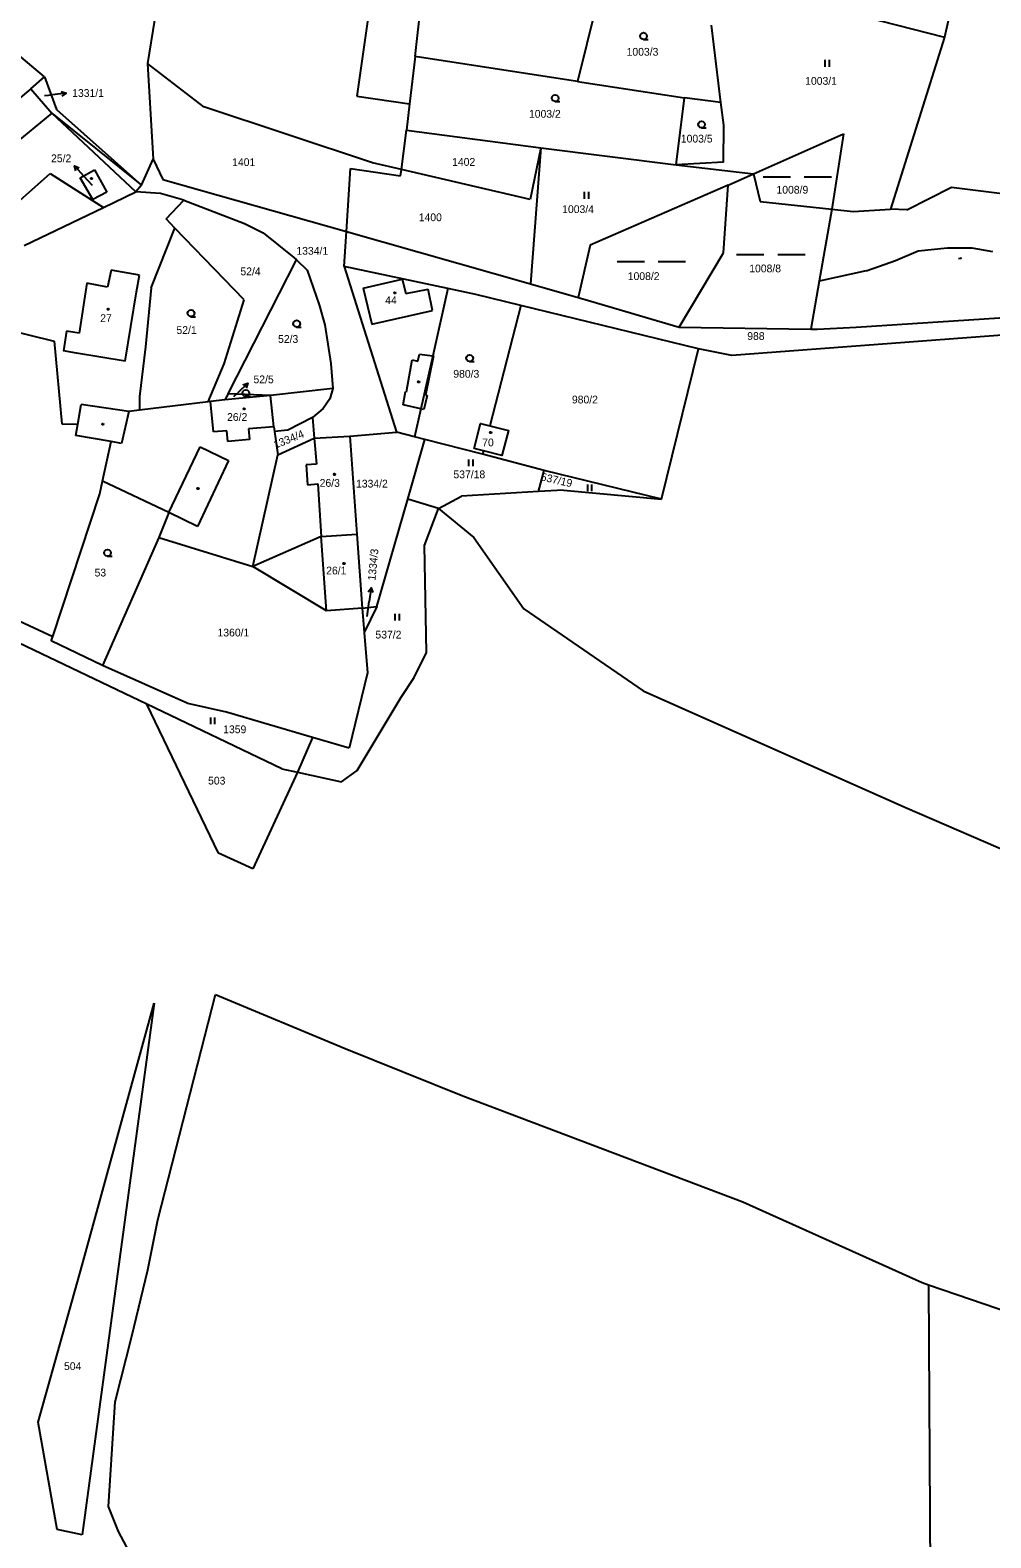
# Model space of a CAD drawing. Extents: x -852001 to -842497, y -1063614 to -1052182.
# Drawn here: x -844473.2 to -844262.9, y -1061856 to -1061526.1 of the extents above; entities that cross this region are included whole.
import ezdxf

# ---------------------------------------------------------------- set-up
doc = ezdxf.new("R2010")
doc.units = 0
for name, color, linetype in [('Default', 7, 'Continuous'), ('KN_HRANICE', 7, 'Continuous'), ('KN_KULTURY', 7, 'Continuous'), ('KN_PARCELY', 7, 'Continuous'), ('KN_SLUCKY', 7, 'Continuous')]:
    doc.layers.add(name, color=color, linetype=linetype)

# ---------------------------------------------------------------- blocks, each defined once
blk = doc.blocks.new('304')
at = {"layer": 'Default'}
blk.add_lwpolyline([(0, 0), (-0.38, 0.1), (-0.65, 0.37), (-0.75, 0.74), (-0.65, 1.11), (-0.38, 1.38), (-0.01, 1.48), (0.36, 1.38), (0.63, 1.11), (0.73, 0.73), (0.63, 0.35), (0.36, 0.08), (-0.02, -0.02), (0.98, -0.02)], dxfattribs=at)
blk = doc.blocks.new('306')
at = {"layer": 'Default'}
for p, q in [((-0.5, 1.5), (-0.5, 0)), ((0.5, 0), (0.5, 1.5))]:
    blk.add_line(p, q, dxfattribs=at)
blk = doc.blocks.new('NAHRADNI_SYMBOL')
at = {"layer": 'Default'}
blk.add_lwpolyline([(0.09, 0.15), (0.18, 0), (0.09, -0.15), (-0.09, -0.15), (-0.18, 0), (-0.09, 0.15), (0.09, 0.15)], dxfattribs=at)
blk = doc.blocks.new('803')
at = {"layer": 'Default'}
for p, q in [((-7.5, 0), (-1.5, 0)), ((1.5, 0), (7.5, 0))]:
    blk.add_line(p, q, dxfattribs=at)
blk = doc.blocks.new('10292')
at = {"layer": 'Default'}
blk.add_line((0, 3), (0, 0), dxfattribs=at)
blk.add_lwpolyline([(-0.5, 2), (0, 3), (0.5, 2)], dxfattribs=at)
blk = doc.blocks.new('402')
at = {"layer": 'Default'}
blk.add_lwpolyline([(0.09, 0.15), (0.18, 0), (0.09, -0.15), (-0.09, -0.15), (-0.18, 0), (-0.09, 0.15), (0.09, 0.15)], dxfattribs=at)
blk = doc.blocks.new('1060')
at = {"layer": 'Default'}
blk.add_line((-0.3, 0), (0.3, 0), dxfattribs=at)
blk.add_lwpolyline([(0.18, 0.04), (0.3, 0), (0.18, -0.04)], dxfattribs=at)

msp = doc.modelspace()

# ---------------------------------------------------------------- linework, layer by layer
at = {"layer": 'KN_HRANICE'}
for p, q in [((-844325.04, -1061514.23), (-844273.04, -1061527.65)), ((-844388.92, -1061531.86), (-844387.54, -1061520.17)), ((-844271.27, -1061519.86), (-844273.04, -1061527.65)), ((-844445.93, -1061523.92), (-844447.49, -1061533.39)), ((-844349.36, -1061521.16), (-844353.34, -1061537.33)), ((-844321.96, -1061541.94), (-844324.04, -1061525.01)), ((-844470, -1061536.35), (-844477.9, -1061529.66)), ((-844273.04, -1061527.65), (-844284.89, -1061565.27)), ((-844435.17, -1061542.92), (-844447.49, -1061533.39)), ((-844447.49, -1061533.39), (-844446.24, -1061554.35)), ((-844388.92, -1061531.86), (-844390.11, -1061542.25)), ((-844353.34, -1061537.33), (-844388.92, -1061531.86)), ((-844473.01, -1061538.94), (-844470, -1061536.35)), ((-844470, -1061536.35), (-844467.4, -1061543.5)), ((-844473.01, -1061538.94), (-844480.27, -1061544.97)), ((-844473.01, -1061538.94), (-844468.42, -1061544.28)), ((-844353.34, -1061537.33), (-844329.92, -1061540.93)), ((-844467.4, -1061543.5), (-844448.75, -1061560.05)), ((-844398.2, -1061555.11), (-844435.17, -1061542.92)), ((-844390.11, -1061542.25), (-844390.76, -1061547.96)), ((-844331.78, -1061555.55), (-844329.92, -1061540.93)), ((-844321.96, -1061541.94), (-844329.92, -1061540.93)), ((-844321.35, -1061546.91), (-844321.96, -1061541.94)), ((-844468.42, -1061544.28), (-844448.75, -1061560.05)), ((-844321.41, -1061554.97), (-844321.35, -1061546.91)), ((-844391.89, -1061556.58), (-844390.76, -1061547.96)), ((-844390.76, -1061547.96), (-844361.35, -1061551.88)), ((-844314.87, -1061557.58), (-844295.15, -1061548.77)), ((-844295.15, -1061548.77), (-844297.72, -1061565.27)), ((-844361.35, -1061551.88), (-844363.72, -1061563.16)), ((-844361.35, -1061551.88), (-844363.66, -1061581.64)), ((-844361.35, -1061551.88), (-844331.78, -1061555.55)), ((-844462.24, -1061558.4), (-844459.06, -1061556.7)), ((-844459.06, -1061556.7), (-844456.35, -1061561.53)), ((-844448.75, -1061560.05), (-844446.24, -1061554.35)), ((-844446.24, -1061554.35), (-844444.11, -1061558.8)), ((-844403.95, -1061570.2), (-844403.02, -1061556.36)), ((-844403.02, -1061556.36), (-844392.07, -1061557.99)), ((-844391.89, -1061556.58), (-844398.2, -1061555.11)), ((-844392.07, -1061557.99), (-844391.89, -1061556.58)), ((-844363.72, -1061563.16), (-844391.89, -1061556.58)), ((-844321.41, -1061554.97), (-844331.78, -1061555.55)), ((-844331.78, -1061555.55), (-844314.87, -1061557.58)), ((-844475.34, -1061563.31), (-844468.77, -1061557.5)), ((-844468.77, -1061557.5), (-844457.13, -1061564.94)), ((-844459.44, -1061563.15), (-844462.24, -1061558.4)), ((-844448.75, -1061560.05), (-844450, -1061561.52)), ((-844444.11, -1061558.8), (-844403.95, -1061570.2)), ((-844320.4, -1061560.02), (-844350.6, -1061573.17)), ((-844321.39, -1061574.83), (-844320.4, -1061560.02)), ((-844320.4, -1061560.02), (-844314.87, -1061557.58)), ((-844314.87, -1061557.58), (-844313.41, -1061563.61)), ((-844456.35, -1061561.53), (-844459.44, -1061563.15)), ((-844457.13, -1061564.94), (-844450, -1061561.52)), ((-844444.59, -1061561.88), (-844450, -1061561.52)), ((-844439.49, -1061563.31), (-844444.59, -1061561.88)), ((-844443.41, -1061567.42), (-844439.49, -1061563.31)), ((-844439.49, -1061563.31), (-844426.27, -1061568.44)), ((-844281.26, -1061565.4), (-844271.49, -1061560.45)), ((-844271.49, -1061560.45), (-844260.43, -1061561.87)), ((-844474.43, -1061573.26), (-844457.13, -1061564.94)), ((-844313.41, -1061563.61), (-844297.72, -1061565.27)), ((-844297.72, -1061565.27), (-844300.47, -1061581.03)), ((-844297.72, -1061565.27), (-844293.03, -1061565.76)), ((-844293.03, -1061565.76), (-844284.89, -1061565.27)), ((-844281.26, -1061565.4), (-844284.89, -1061565.27)), ((-844446.64, -1061582.48), (-844441.46, -1061569.44)), ((-844441.46, -1061569.44), (-844443.41, -1061567.42)), ((-844426.34, -1061585.08), (-844441.46, -1061569.44)), ((-844426.27, -1061568.44), (-844422.18, -1061570.43)), ((-844422.18, -1061570.43), (-844415.41, -1061575.89)), ((-844404.46, -1061577.82), (-844403.95, -1061570.2)), ((-844403.95, -1061570.2), (-844363.66, -1061581.64)), ((-844350.6, -1061573.17), (-844353.2, -1061584.61)), ((-844429.81, -1061605.69), (-844414.88, -1061576.38)), ((-844415.41, -1061575.89), (-844414.88, -1061576.38)), ((-844414.88, -1061576.38), (-844412.5, -1061578.61)), ((-844331.11, -1061591.08), (-844321.39, -1061574.83)), ((-844412.5, -1061578.61), (-844409.87, -1061586.18)), ((-844404.46, -1061577.82), (-844393, -1061614.07)), ((-844381.76, -1061582.63), (-844404.46, -1061577.82)), ((-844446.64, -1061582.48), (-844447.87, -1061595.38)), ((-844381.76, -1061582.63), (-844385.04, -1061597.34)), ((-844375.58, -1061583.94), (-844381.76, -1061582.63)), ((-844363.66, -1061581.64), (-844353.2, -1061584.61)), ((-844300.47, -1061581.03), (-844302.31, -1061591.53)), ((-844430.7, -1061599.13), (-844426.34, -1061585.08)), ((-844409.87, -1061586.18), (-844408.69, -1061590.57)), ((-844365.77, -1061586.33), (-844375.58, -1061583.94)), ((-844365.77, -1061586.33), (-844372.54, -1061612.69)), ((-844326.87, -1061595.82), (-844365.77, -1061586.33)), ((-844353.2, -1061584.61), (-844351.68, -1061585.04)), ((-844351.68, -1061585.04), (-844331.11, -1061591.08)), ((-844292.4, -1061591.06), (-844254.72, -1061588.66)), ((-844478.86, -1061591.44), (-844467.93, -1061594.19)), ((-844408.69, -1061590.57), (-844407.36, -1061599.06)), ((-844331.11, -1061591.08), (-844302.31, -1061591.53)), ((-844255.5, -1061592.46), (-844319.6, -1061597.27)), ((-844302.31, -1061591.53), (-844300.94, -1061591.55)), ((-844300.94, -1061591.55), (-844292.4, -1061591.06)), ((-844467.93, -1061594.19), (-844466.24, -1061612.23)), ((-844447.87, -1061595.38), (-844449.19, -1061606.24)), ((-844334.99, -1061628.71), (-844326.87, -1061595.82)), ((-844319.6, -1061597.27), (-844326.87, -1061595.82)), ((-844434.17, -1061607.4), (-844430.7, -1061599.13)), ((-844407.36, -1061599.06), (-844406.9, -1061604.52)), ((-844385.04, -1061597.34), (-844387.63, -1061608.98)), ((-844449.19, -1061606.24), (-844449.19, -1061609.24)), ((-844429.81, -1061605.69), (-844430.56, -1061607.03)), ((-844420.55, -1061606.03), (-844430.56, -1061607.03)), ((-844420.55, -1061606.03), (-844429.81, -1061605.69)), ((-844406.9, -1061604.52), (-844420.55, -1061606.03)), ((-844406.9, -1061604.52), (-844407.58, -1061606.77)), ((-844451.53, -1061609.53), (-844453.15, -1061616.52)), ((-844449.19, -1061609.24), (-844451.53, -1061609.53)), ((-844434.17, -1061607.4), (-844449.19, -1061609.24)), ((-844433.67, -1061607.34), (-844434.17, -1061607.4)), ((-844430.56, -1061607.03), (-844433.67, -1061607.34)), ((-844409.04, -1061608.91), (-844411.39, -1061610.86)), ((-844407.58, -1061606.77), (-844409.04, -1061608.91)), ((-844387.63, -1061608.98), (-844389, -1061615.11)), ((-844466.24, -1061612.23), (-844462.73, -1061612.31)), ((-844463.16, -1061614.78), (-844462.73, -1061612.31)), ((-844411.39, -1061610.86), (-844416.78, -1061613.62)), ((-844411.39, -1061610.86), (-844410.98, -1061615.41)), ((-844455.44, -1061616.12), (-844463.16, -1061614.78)), ((-844457.28, -1061624.8), (-844455.44, -1061616.12)), ((-844453.15, -1061616.52), (-844455.44, -1061616.12)), ((-844416.78, -1061613.62), (-844419.7, -1061613.9)), ((-844419.7, -1061613.9), (-844418.97, -1061619.01)), ((-844418.97, -1061619.01), (-844410.98, -1061615.41)), ((-844410.98, -1061615.41), (-844403.17, -1061614.92)), ((-844403.17, -1061614.92), (-844393, -1061614.07)), ((-844403.17, -1061614.92), (-844401.63, -1061636.37)), ((-844389, -1061615.11), (-844393, -1061614.07)), ((-844390.52, -1061628.76), (-844386.76, -1061615.69)), ((-844386.76, -1061615.69), (-844389, -1061615.11)), ((-844374.13, -1061618.87), (-844386.76, -1061615.69)), ((-844424.43, -1061643.44), (-844418.97, -1061619.01)), ((-844373.95, -1061618.15), (-844375.97, -1061617.63)), ((-844373.95, -1061618.15), (-844374.13, -1061618.87)), ((-844360.67, -1061622.48), (-844374.13, -1061618.87)), ((-844361.86, -1061627.06), (-844360.67, -1061622.48)), ((-844334.99, -1061628.71), (-844360.67, -1061622.48)), ((-844457.87, -1061627.58), (-844457.28, -1061624.8)), ((-844442.81, -1061631.67), (-844457.28, -1061624.8)), ((-844468.22, -1061658.79), (-844457.87, -1061627.58)), ((-844397.26, -1061652.22), (-844390.52, -1061628.76)), ((-844383.79, -1061630.77), (-844390.52, -1061628.76)), ((-844383.79, -1061630.77), (-844378.77, -1061628.06)), ((-844361.86, -1061627.06), (-844378.77, -1061628.06)), ((-844356.45, -1061626.74), (-844361.86, -1061627.06)), ((-844356.45, -1061626.74), (-844334.99, -1061628.71)), ((-844442.81, -1061631.67), (-844445.01, -1061637.13)), ((-844386.84, -1061638.84), (-844383.79, -1061630.77)), ((-844383.79, -1061630.77), (-844376.04, -1061637.09)), ((-844445.01, -1061637.13), (-844457.31, -1061665.08)), ((-844445.01, -1061637.13), (-844424.43, -1061643.44)), ((-844409.45, -1061636.9), (-844424.43, -1061643.44)), ((-844409.45, -1061636.9), (-844401.63, -1061636.37)), ((-844401.63, -1061636.37), (-844400.47, -1061652.6)), ((-844386.4, -1061662.29), (-844386.84, -1061638.84)), ((-844376.04, -1061637.09), (-844365.11, -1061652.71)), ((-844498.37, -1061644.75), (-844468.22, -1061658.79)), ((-844408.29, -1061653.16), (-844424.43, -1061643.44)), ((-844447.63, -1061673.57), (-844500.09, -1061648.51)), ((-844400.47, -1061652.6), (-844397.26, -1061652.22)), ((-844397.26, -1061652.22), (-844400.04, -1061657.86)), ((-844400.47, -1061652.6), (-844408.29, -1061653.16)), ((-844400.47, -1061652.6), (-844400.04, -1061657.86)), ((-844365.11, -1061652.71), (-844338.96, -1061670.68)), ((-844468.52, -1061659.69), (-844468.22, -1061658.79)), ((-844400.04, -1061657.86), (-844399.31, -1061666.7)), ((-844457.31, -1061665.08), (-844468.52, -1061659.69)), ((-844389.07, -1061667.77), (-844386.4, -1061662.29)), ((-844438.63, -1061673.4), (-844457.31, -1061665.08)), ((-844399.31, -1061666.7), (-844403.35, -1061683.2)), ((-844391.94, -1061672.06), (-844389.07, -1061667.77)), ((-844401.55, -1061688.12), (-844391.94, -1061672.06)), ((-844338.96, -1061670.68), (-844281.72, -1061696.14)), ((-844418.06, -1061687.7), (-844447.63, -1061673.57)), ((-844431.96, -1061706.15), (-844447.63, -1061673.57)), ((-844430.19, -1061675.35), (-844438.63, -1061673.4)), ((-844411.36, -1061680.86), (-844430.19, -1061675.35)), ((-844411.36, -1061680.86), (-844414.65, -1061688.46)), ((-844403.35, -1061683.2), (-844411.36, -1061680.86)), ((-844414.65, -1061688.46), (-844424.45, -1061709.57)), ((-844418.06, -1061687.7), (-844414.65, -1061688.46)), ((-844414.65, -1061688.46), (-844405.04, -1061690.59)), ((-844405.04, -1061690.59), (-844401.55, -1061688.12)), ((-844281.72, -1061696.14), (-844251.79, -1061709.03)), ((-844424.45, -1061709.57), (-844431.96, -1061706.15)), ((-844445.21, -1061786.38), (-844432.58, -1061737.13)), ((-844432.58, -1061737.13), (-844404.23, -1061748.89)), ((-844446.01, -1061738.96), (-844461.75, -1061855.31)), ((-844461.75, -1061796.28), (-844446.01, -1061738.96)), ((-844404.23, -1061748.89), (-844378.49, -1061759.27)), ((-844378.49, -1061759.27), (-844317.17, -1061782.48)), ((-844317.17, -1061782.48), (-844277.96, -1061800.13)), ((-844447.39, -1061797.31), (-844445.21, -1061786.38)), ((-844471.43, -1061830.64), (-844461.75, -1061796.28)), ((-844450.86, -1061811.85), (-844447.39, -1061797.31)), ((-844277.96, -1061800.13), (-844276.55, -1061800.61)), ((-844276.55, -1061800.61), (-844242.58, -1061812.17)), ((-844276.55, -1061800.61), (-844275.61, -1061955.01)), ((-844454.58, -1061826.21), (-844450.86, -1061811.85)), ((-844455.99, -1061849.08), (-844454.58, -1061826.21)), ((-844467.25, -1061854.17), (-844471.43, -1061830.64)), ((-844453.81, -1061854.57), (-844455.99, -1061849.08)), ((-844461.75, -1061855.31), (-844467.25, -1061854.17)), ((-844441.86, -1061877.08), (-844453.81, -1061854.57))]:
    msp.add_line(p, q, dxfattribs=at)
for points in [[(-844375.97, -1061617.63), (-844374.57, -1061612.18), (-844372.54, -1061612.69)], [(-844372.54, -1061612.69), (-844368.49, -1061613.72), (-844369.9, -1061619.19), (-844373.95, -1061618.15)]]:
    msp.add_lwpolyline(points, dxfattribs=at)
at = {"layer": 'KN_PARCELY'}
for p, q in [((-844470.04, -1061540.44), (-844468.27, -1061540.25)), ((-844459.49, -1061560.13), (-844461.41, -1061558.03)), ((-844428.56, -1061606.28), (-844427.68, -1061605.44)), ((-844399.36, -1061654.37), (-844398.93, -1061651.08))]:
    msp.add_line(p, q, dxfattribs=at)
at = {"layer": 'KN_SLUCKY'}
for p, q in [((-844399.03, -1061522.17), (-844401.68, -1061540.59)), ((-844401.68, -1061540.59), (-844390.11, -1061542.25)), ((-844468.42, -1061544.28), (-844475.84, -1061550.39)), ((-844450, -1061561.52), (-844468.42, -1061544.28)), ((-844287.3, -1061577.72), (-844283.8, -1061576.51)), ((-844283.8, -1061576.51), (-844278.78, -1061574.38)), ((-844278.78, -1061574.38), (-844272.39, -1061573.77)), ((-844272.39, -1061573.77), (-844267.07, -1061573.77)), ((-844267.07, -1061573.77), (-844262.5, -1061574.53)), ((-844455.44, -1061578.66), (-844456.23, -1061582.31)), ((-844449.21, -1061579.73), (-844455.44, -1061578.66)), ((-844449.84, -1061583.39), (-844449.21, -1061579.73)), ((-844290.2, -1061578.79), (-844300.47, -1061581.03)), ((-844290.2, -1061578.79), (-844287.3, -1061577.72)), ((-844460.74, -1061581.49), (-844462.44, -1061592.38)), ((-844456.23, -1061582.31), (-844460.74, -1061581.49)), ((-844400.24, -1061582.58), (-844391.7, -1061580.59)), ((-844400.24, -1061582.58), (-844398.4, -1061590.46)), ((-844391.7, -1061580.59), (-844390.96, -1061583.76)), ((-844390.96, -1061583.76), (-844386.07, -1061582.78)), ((-844385.09, -1061587.46), (-844386.07, -1061582.78)), ((-844452.33, -1061598.56), (-844449.84, -1061583.39)), ((-844398.4, -1061590.46), (-844385.09, -1061587.46)), ((-844465.16, -1061591.96), (-844465.85, -1061596.27)), ((-844462.44, -1061592.38), (-844465.16, -1061591.96)), ((-844463.04, -1061596.75), (-844465.85, -1061596.27)), ((-844452.33, -1061598.56), (-844463.04, -1061596.75)), ((-844390.81, -1061605.22), (-844389.57, -1061598.27)), ((-844389.57, -1061598.27), (-844388.27, -1061598.54)), ((-844388.27, -1061598.54), (-844387.95, -1061597.02)), ((-844387.95, -1061597.02), (-844385.04, -1061597.34)), ((-844384.89, -1061597.36), (-844386.59, -1061605.98)), ((-844385.04, -1061597.34), (-844384.89, -1061597.36)), ((-844419.85, -1061612.89), (-844420.55, -1061606.03)), ((-844391.51, -1061608.12), (-844390.99, -1061605.19)), ((-844390.99, -1061605.19), (-844390.81, -1061605.22)), ((-844386.24, -1061606.04), (-844386.99, -1061609.12)), ((-844386.59, -1061605.98), (-844386.24, -1061606.04)), ((-844462.73, -1061612.31), (-844461.98, -1061607.98)), ((-844451.53, -1061609.53), (-844461.98, -1061607.98)), ((-844433, -1061614.02), (-844433.67, -1061607.34)), ((-844387.63, -1061608.98), (-844391.51, -1061608.12)), ((-844386.99, -1061609.12), (-844387.63, -1061608.98)), ((-844419.85, -1061612.89), (-844425.33, -1061613.36)), ((-844419.85, -1061612.89), (-844419.7, -1061613.9)), ((-844430.09, -1061613.77), (-844433, -1061614.02)), ((-844429.89, -1061616.09), (-844430.09, -1061613.77)), ((-844425.13, -1061615.69), (-844429.89, -1061616.09)), ((-844425.33, -1061613.36), (-844425.13, -1061615.69)), ((-844410.98, -1061615.41), (-844410.49, -1061621.05)), ((-844442.81, -1061631.67), (-844435.96, -1061617.24)), ((-844435.96, -1061617.24), (-844429.76, -1061620.26)), ((-844429.76, -1061620.26), (-844436.5, -1061634.67)), ((-844410.49, -1061621.05), (-844412.76, -1061621.25)), ((-844412.76, -1061621.25), (-844412.46, -1061625.56)), ((-844412.46, -1061625.56), (-844410.21, -1061625.4)), ((-844410.21, -1061625.4), (-844409.45, -1061636.9)), ((-844436.5, -1061634.67), (-844442.81, -1061631.67)), ((-844408.29, -1061653.16), (-844409.45, -1061636.9))]:
    msp.add_line(p, q, dxfattribs=at)

# ---------------------------------------------------------------- block references
at = {"layer": 'KN_KULTURY'}
for name, p in [('304', (-844338.91, -1061528.14)), ('306', (-844298.71, -1061534.13)), ('304', (-844358.24, -1061541.71)), ('304', (-844326.19, -1061547.48)), ('NAHRADNI_SYMBOL', (-844459.73, -1061558.6)), ('803', (-844305.24, -1061558.19)), ('306', (-844351.38, -1061563)), ('803', (-844311.05, -1061575.18)), ('803', (-844337.19, -1061576.75)), ('402', (-844393.34, -1061583.56)), ('402', (-844456.09, -1061587.13)), ('304', (-844437.93, -1061588.79)), ('304', (-844414.81, -1061591.07)), ('304', (-844376.96, -1061598.61)), ('402', (-844388.12, -1061603.08)), ('304', (-844425.93, -1061606.27)), ('402', (-844426.32, -1061608.99)), ('402', (-844457.25, -1061612.33)), ('402', (-844372.37, -1061614.17)), ('306', (-844376.68, -1061621.53)), ('402', (-844406.53, -1061623.29)), ('306', (-844350.69, -1061626.99)), ('402', (-844436.41, -1061626.42)), ('304', (-844456.2, -1061641.19)), ('402', (-844404.47, -1061642.81)), ('306', (-844392.82, -1061655.28)), ('306', (-844433.21, -1061677.96))]:
    msp.add_blockref(name, p, dxfattribs=at)
at = {"layer": 'KN_PARCELY'}
for name, p, rotation in [('10292', (-844468.27, -1061540.25), -83.77704700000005), ('10292', (-844461.41, -1061558.03), 42.341581), ('1060', (-844269.71, -1061576.03), 2.979381), ('10292', (-844427.68, -1061605.44), -46.36290299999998), ('10292', (-844398.93, -1061651.08), -7.3444769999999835)]:
    msp.add_blockref(name, p, dxfattribs=dict(at, rotation=rotation))

# ---------------------------------------------------------------- texts
for s, height, p in [('1003/3', 1.7, (-844342.61, -1061531.7)), ('1003/1', 1.7, (-844303.53, -1061538.07)), ('1331/1', 0.1, (-844470.32, -1061540.44)), ('1331/1', 1.7, (-844463.95, -1061540.72)), ('1003/2', 1.7, (-844363.98, -1061545.27)), ('1003/5', 1.7, (-844330.74, -1061550.7)), ('25/2', 1.7, (-844468.57, -1061555.01)), ('1401', 1.7, (-844428.94, -1061555.84)), ('1402', 1.7, (-844380.8, -1061555.8)), ('25/2', 0.1, (-844459.69, -1061560.13)), ('1008/9', 1.7, (-844309.81, -1061561.88)), ('1400', 1.7, (-844388.1, -1061567.91)), ('1003/4', 1.7, (-844356.71, -1061566.13)), ('1334/1', 1.7, (-844414.88, -1061575.24)), ('52/4', 1.7, (-844427.13, -1061579.74)), ('1008/2', 1.7, (-844342.36, -1061580.78)), ('1008/8', 1.7, (-844315.77, -1061579.1)), ('44', 1.7, (-844395.44, -1061586.03)), ('27', 1.7, (-844457.82, -1061589.97)), ('52/1', 1.7, (-844441.13, -1061592.59)), ('52/3', 1.7, (-844418.9, -1061594.54)), ('988', 1.7, (-844316.21, -1061593.89)), ('52/5', 1.7, (-844424.27, -1061603.37)), ('980/3', 1.7, (-844380.54, -1061602.15)), ('52/5', 0.1, (-844428.76, -1061606.28)), ('980/2', 1.7, (-844354.58, -1061607.78)), ('26/2', 1.7, (-844430.05, -1061611.6)), ('70', 1.7, (-844374.21, -1061617.16)), ('537/18', 1.7, (-844380.51, -1061624.15)), ('26/3', 1.7, (-844409.79, -1061626.02)), ('1334/2', 1.7, (-844401.83, -1061626.18)), ('53', 1.7, (-844459.05, -1061645.64)), ('26/1', 1.7, (-844408.36, -1061645.19)), ('1334/3', 0.1, (-844399.66, -1061654.37)), ('1360/1', 1.7, (-844432.14, -1061658.76)), ('537/2', 1.7, (-844397.58, -1061659.21)), ('1359', 1.7, (-844430.9, -1061679.93)), ('503', 1.7, (-844434.21, -1061691.16)), ('504', 1.7, (-844465.74, -1061819.25))]:
    msp.add_text(s, height=height, dxfattribs=at).set_placement(p)
for s, rotation, p in [('1334/4', 22.059, (-844419.47, -1061617.7)), ('537/19', 347.155, (-844361.51, -1061624.59)), ('1334/3', 84.454, (-844397.59, -1061646.58))]:
    msp.add_text(s, height=1.7, rotation=rotation, dxfattribs=at).set_placement(p)

doc.saveas('drawing.dxf')
